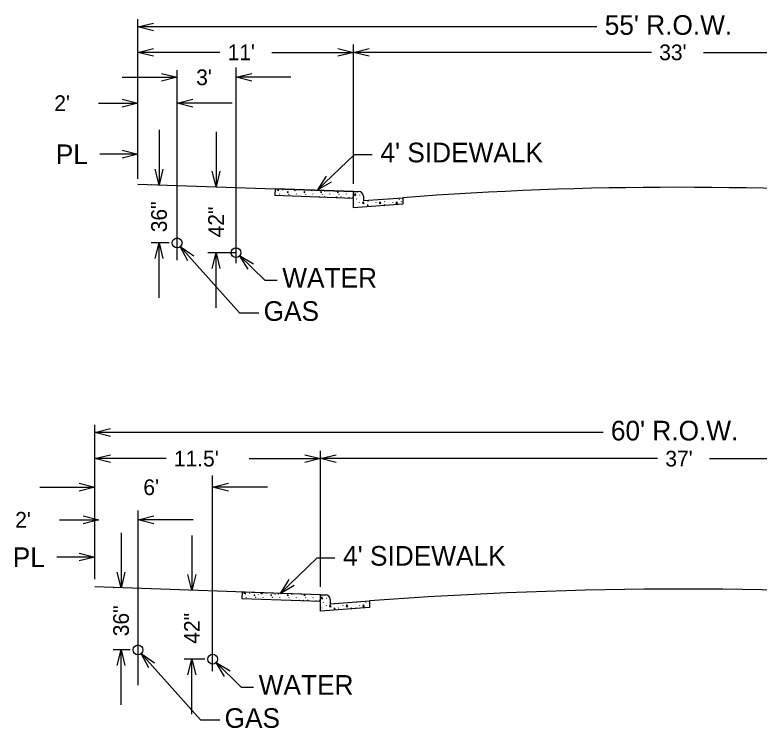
# Model space of a CAD drawing. Extents: x 524397 to 525117, y 3701341 to 3701821.
# Drawn here: x 524722.9 to 524798.7, y 3701506.1 to 3701578.8 of the extents above; entities that cross this region are included whole.
import ezdxf

# ---------------------------------------------------------------- set-up
doc = ezdxf.new("R2010")
doc.units = 0
doc.layers.add('Level 11', color=7, linetype='Continuous')

msp = doc.modelspace()

# ---------------------------------------------------------------- linework, layer by layer
at = {"layer": 'Level 11'}
for p, q in [((524735.411, 3701562.373), (524735.411, 3701578.385)), ((524735.411, 3701577.585), (524737.012, 3701577.985)), ((524782.191, 3701577.585), (524735.411, 3701577.585)), ((524737.012, 3701577.185), (524735.411, 3701577.585)), ((524735.411, 3701562.373), (524735.411, 3701575.796)), ((524757.398, 3701561.605), (524757.398, 3701575.796)), ((524735.411, 3701574.995), (524737.012, 3701575.396)), ((524743.751, 3701574.995), (524735.411, 3701574.995)), ((524737.012, 3701574.595), (524735.411, 3701574.995)), ((524749.058, 3701574.995), (524757.398, 3701574.995)), ((524755.797, 3701575.396), (524757.398, 3701574.995)), ((524757.398, 3701574.995), (524755.797, 3701574.595)), ((524757.398, 3701574.995), (524758.999, 3701575.396)), ((524787.744, 3701574.995), (524757.398, 3701574.995)), ((524758.999, 3701574.595), (524757.398, 3701574.995)), ((524793.051, 3701574.995), (524823.398, 3701574.995)), ((524745.411, 3701553.501), (524745.411, 3701573.437)), ((524737.81, 3701572.854), (524739.411, 3701572.454)), ((524739.411, 3701553.8), (524739.411, 3701573.178)), ((524745.411, 3701572.454), (524747.012, 3701572.854)), ((524733.808, 3701572.454), (524739.411, 3701572.454)), ((524739.411, 3701572.454), (524737.81, 3701572.053)), ((524751.015, 3701572.454), (524745.411, 3701572.454)), ((524747.012, 3701572.053), (524745.411, 3701572.454)), ((524731.409, 3701569.815), (524735.411, 3701569.815)), ((524733.81, 3701570.215), (524735.411, 3701569.815)), ((524735.411, 3701569.815), (524733.81, 3701569.415)), ((524739.411, 3701569.815), (524741.012, 3701570.215)), ((524745.015, 3701569.815), (524739.411, 3701569.815)), ((524741.012, 3701569.415), (524739.411, 3701569.815)), ((524735.411, 3701562.088), (524735.411, 3701569.337)), ((524739.411, 3701556.088), (524739.411, 3701569.337)), ((524737.565, 3701567.099), (524737.565, 3701561.496)), ((524743.375, 3701566.897), (524743.375, 3701561.294)), ((524733.81, 3701565.02), (524735.411, 3701564.62)), ((524735.411, 3701564.62), (524731.535, 3701564.62)), ((524735.411, 3701564.62), (524733.81, 3701564.22)), ((524753.712, 3701560.967), (524757.491, 3701564.578)), ((524757.491, 3701564.578), (524759.296, 3701564.578)), ((524737.565, 3701561.496), (524737.165, 3701563.097)), ((524737.965, 3701563.097), (524737.565, 3701561.496)), ((524743.375, 3701561.294), (524742.975, 3701562.895)), ((524743.775, 3701562.895), (524743.375, 3701561.294)), ((524754.593, 3701562.362), (524753.712, 3701560.967)), ((524735.411, 3701561.572), (524757.398, 3701560.804)), ((524736.794, 3701561.496), (524736.765, 3701561.496)), ((524742.576, 3701561.294), (524742.575, 3701561.294)), ((524753.712, 3701560.967), (524755.146, 3701561.783)), ((524749.403, 3701561.084), (524749.379, 3701560.424)), ((524757.398, 3701560.804), (524749.403, 3701561.084)), ((524749.866, 3701560.538), (524749.852, 3701560.57)), ((524750.19, 3701560.95), (524750.175, 3701560.982)), ((524750.79, 3701560.53), (524750.776, 3701560.509)), ((524750.804, 3701560.538), (524750.79, 3701560.517)), ((524751.047, 3701560.861), (524751.043, 3701560.829)), ((524751.568, 3701560.538), (524751.554, 3701560.57)), ((524751.891, 3701560.95), (524751.877, 3701560.982)), ((524752.491, 3701560.53), (524752.477, 3701560.509)), ((524752.506, 3701560.538), (524752.491, 3701560.517)), ((524752.748, 3701560.861), (524752.745, 3701560.829)), ((524753.269, 3701560.538), (524753.255, 3701560.57)), ((524754.193, 3701560.53), (524754.179, 3701560.509)), ((524754.207, 3701560.538), (524754.193, 3701560.517)), ((524754.45, 3701560.861), (524754.446, 3701560.829)), ((524754.971, 3701560.538), (524754.957, 3701560.57)), ((524755.894, 3701560.53), (524755.88, 3701560.509)), ((524755.909, 3701560.538), (524755.894, 3701560.517)), ((524756.15, 3701560.848), (524756.148, 3701560.829)), ((524756.672, 3701560.538), (524756.658, 3701560.57)), ((524757.398, 3701559.143), (524757.398, 3701560.804)), ((524757.398, 3701560.804), (524757.911, 3701560.804)), ((524757.398, 3701560.144), (524757.398, 3701560.804)), ((524757.911, 3701560.804), (524757.898, 3701560.804)), ((524758.04, 3701560.445), (524758.026, 3701560.477)), ((524749.379, 3701560.424), (524757.398, 3701560.144)), ((524754.417, 3701560.275), (524754.403, 3701560.307)), ((524755.247, 3701560.219), (524755.244, 3701560.225)), ((524756.118, 3701560.275), (524756.104, 3701560.307)), ((524756.96, 3701560.193), (524756.946, 3701560.225)), ((524757.717, 3701560.033), (524757.703, 3701560.065)), ((524758.005, 3701559.688), (524757.99, 3701559.72)), ((524758.398, 3701560.342), (524758.398, 3701559.88)), ((524758.398, 3701559.88), (524762.398, 3701560.182)), ((524758.864, 3701559.77), (524758.85, 3701559.802)), ((524759.706, 3701559.688), (524759.692, 3701559.72)), ((524760.342, 3701560.025), (524760.328, 3701560.004)), ((524760.352, 3701560.027), (524760.342, 3701560.012)), ((524760.566, 3701559.77), (524760.551, 3701559.802)), ((524761.12, 3701560.033), (524761.106, 3701560.065)), ((524761.408, 3701559.688), (524761.393, 3701559.72)), ((524762.043, 3701560.025), (524762.029, 3701560.004)), ((524762.058, 3701560.033), (524762.043, 3701560.012)), ((524762.267, 3701559.77), (524762.253, 3701559.802)), ((524762.398, 3701560.182), (524762.398, 3701559.52)), ((524762.398, 3701559.52), (524757.398, 3701559.143)), ((524757.561, 3701559.461), (524757.546, 3701559.44)), ((524759.262, 3701559.461), (524759.248, 3701559.44)), ((524760.964, 3701559.461), (524760.949, 3701559.44)), ((524738.611, 3701555.572), (524736.765, 3701555.572)), ((524737.165, 3701553.971), (524737.565, 3701555.572)), ((524737.565, 3701549.968), (524737.565, 3701555.572)), ((524737.565, 3701555.572), (524737.965, 3701553.971)), ((524739.411, 3701555.464), (524739.411, 3701555.549)), ((524740.503, 3701553.731), (524739.736, 3701555.192)), ((524739.736, 3701555.192), (524741.1, 3701554.264)), ((524739.736, 3701555.192), (524745.766, 3701548.436)), ((524745.411, 3701554.568), (524742.549, 3701554.568)), ((524744.611, 3701554.572), (524742.575, 3701554.572)), ((524742.975, 3701552.971), (524743.375, 3701554.572)), ((524743.375, 3701548.968), (524743.375, 3701554.572)), ((524743.375, 3701554.572), (524743.775, 3701552.971)), ((524746.649, 3701552.879), (524745.781, 3701554.283)), ((524745.781, 3701554.283), (524747.207, 3701553.453)), ((524745.781, 3701554.283), (524748.346, 3701551.784)), ((524748.346, 3701551.784), (524749.592, 3701551.784)), ((524745.766, 3701548.436), (524747.754, 3701548.436)), ((524731.022, 3701521.302), (524731.022, 3701537.038)), ((524731.022, 3701536.238), (524732.623, 3701536.638)), ((524782.816, 3701536.238), (524731.022, 3701536.238)), ((524732.623, 3701535.838), (524731.022, 3701536.238)), ((524731.022, 3701521.302), (524731.022, 3701534.384)), ((524731.022, 3701533.584), (524732.623, 3701533.984)), ((524752.416, 3701533.984), (524754.017, 3701533.584)), ((524754.017, 3701520.499), (524754.017, 3701534.384)), ((524754.017, 3701533.584), (524755.618, 3701533.984)), ((524738.278, 3701533.584), (524731.022, 3701533.584)), ((524732.623, 3701533.183), (524731.022, 3701533.584)), ((524746.762, 3701533.584), (524754.017, 3701533.584)), ((524754.017, 3701533.584), (524752.416, 3701533.183)), ((524788.366, 3701533.584), (524754.017, 3701533.584)), ((524755.618, 3701533.183), (524754.017, 3701533.584)), ((524793.673, 3701533.584), (524828.022, 3701533.584)), ((524743.03, 3701511.919), (524743.03, 3701531.856)), ((524729.421, 3701531.071), (524731.022, 3701530.671)), ((524743.03, 3701530.671), (524744.631, 3701531.071)), ((524725.419, 3701530.671), (524731.022, 3701530.671)), ((524731.022, 3701530.671), (524729.421, 3701530.271)), ((524748.634, 3701530.671), (524743.03, 3701530.671)), ((524744.631, 3701530.271), (524743.03, 3701530.671)), ((524735.43, 3701510.504), (524735.43, 3701528.3)), ((524727.427, 3701527.352), (524731.43, 3701527.352)), ((524729.829, 3701527.752), (524731.43, 3701527.352)), ((524731.43, 3701527.352), (524729.829, 3701526.952)), ((524735.43, 3701527.352), (524737.031, 3701527.752)), ((524741.034, 3701527.352), (524735.43, 3701527.352)), ((524737.031, 3701526.952), (524735.43, 3701527.352)), ((524733.693, 3701526.012), (524733.693, 3701520.408)), ((524740.918, 3701525.759), (524740.918, 3701520.156)), ((524731.022, 3701523.55), (524727.146, 3701523.55)), ((524729.421, 3701523.95), (524731.022, 3701523.55)), ((524731.022, 3701523.55), (524729.421, 3701523.15)), ((524749.904, 3701519.853), (524753.683, 3701523.464)), ((524753.683, 3701523.464), (524755.488, 3701523.464)), ((524733.693, 3701520.408), (524733.292, 3701522.009)), ((524734.093, 3701522.009), (524733.693, 3701520.408)), ((524740.918, 3701520.156), (524740.518, 3701521.757)), ((524741.318, 3701521.757), (524740.918, 3701520.156)), ((524750.785, 3701521.248), (524749.904, 3701519.853)), ((524754.017, 3701519.699), (524731.022, 3701520.502)), ((524732.915, 3701520.408), (524732.892, 3701520.408)), ((524749.904, 3701519.853), (524751.338, 3701520.669)), ((524740.142, 3701520.156), (524740.118, 3701520.156)), ((524746.022, 3701519.978), (524745.999, 3701519.319)), ((524754.017, 3701519.699), (524746.022, 3701519.978)), ((524746.809, 3701519.845), (524746.795, 3701519.877)), ((524747.666, 3701519.756), (524747.663, 3701519.724)), ((524748.511, 3701519.845), (524748.497, 3701519.877)), ((524749.368, 3701519.756), (524749.364, 3701519.724)), ((524751.069, 3701519.756), (524751.066, 3701519.724)), ((524752.769, 3701519.742), (524752.767, 3701519.724)), ((524754.017, 3701518.037), (524754.017, 3701519.699)), ((524754.017, 3701519.699), (524754.531, 3701519.699)), ((524754.017, 3701519.039), (524754.017, 3701519.699)), ((524754.531, 3701519.699), (524754.517, 3701519.699)), ((524745.999, 3701519.319), (524754.017, 3701519.039)), ((524746.486, 3701519.433), (524746.472, 3701519.465)), ((524747.41, 3701519.425), (524747.395, 3701519.404)), ((524747.424, 3701519.433), (524747.41, 3701519.412)), ((524748.188, 3701519.433), (524748.173, 3701519.465)), ((524749.111, 3701519.425), (524749.097, 3701519.404)), ((524749.125, 3701519.433), (524749.111, 3701519.412)), ((524749.889, 3701519.433), (524749.875, 3701519.465)), ((524750.813, 3701519.425), (524750.798, 3701519.404)), ((524750.827, 3701519.433), (524750.813, 3701519.412)), ((524751.037, 3701519.17), (524751.022, 3701519.202)), ((524751.591, 3701519.433), (524751.576, 3701519.465)), ((524751.867, 3701519.114), (524751.864, 3701519.12)), ((524752.514, 3701519.425), (524752.5, 3701519.404)), ((524752.528, 3701519.433), (524752.514, 3701519.412)), ((524752.738, 3701519.17), (524752.724, 3701519.202)), ((524753.292, 3701519.433), (524753.278, 3701519.465)), ((524753.58, 3701519.088), (524753.566, 3701519.12)), ((524754.337, 3701518.928), (524754.322, 3701518.96)), ((524754.66, 3701519.34), (524754.646, 3701519.372)), ((524755.017, 3701519.237), (524755.017, 3701518.774)), ((524755.017, 3701518.774), (524759.017, 3701519.076)), ((524756.962, 3701518.92), (524756.947, 3701518.898)), ((524756.972, 3701518.922), (524756.962, 3701518.907)), ((524757.74, 3701518.928), (524757.725, 3701518.96)), ((524758.663, 3701518.92), (524758.649, 3701518.898)), ((524758.677, 3701518.928), (524758.663, 3701518.907)), ((524759.017, 3701519.076), (524759.017, 3701518.415)), ((524759.017, 3701518.415), (524754.017, 3701518.037)), ((524754.18, 3701518.356), (524754.166, 3701518.334)), ((524754.624, 3701518.583), (524754.61, 3701518.615)), ((524755.484, 3701518.665), (524755.47, 3701518.697)), ((524755.882, 3701518.356), (524755.868, 3701518.334)), ((524756.326, 3701518.583), (524756.312, 3701518.615)), ((524757.185, 3701518.665), (524757.171, 3701518.697)), ((524757.583, 3701518.356), (524757.569, 3701518.334)), ((524758.027, 3701518.583), (524758.013, 3701518.615)), ((524758.887, 3701518.665), (524758.873, 3701518.697)), ((524734.63, 3701514.087), (524732.892, 3701514.087)), ((524733.292, 3701512.486), (524733.693, 3701514.087)), ((524733.693, 3701508.484), (524733.693, 3701514.087)), ((524733.693, 3701514.087), (524734.093, 3701512.486)), ((524736.522, 3701512.246), (524735.754, 3701513.707)), ((524735.754, 3701513.707), (524737.119, 3701512.779)), ((524735.754, 3701513.707), (524741.785, 3701506.952)), ((524742.23, 3701513.144), (524740.118, 3701513.144)), ((524740.518, 3701511.543), (524740.918, 3701513.144)), ((524740.918, 3701507.54), (524740.918, 3701513.144)), ((524740.918, 3701513.144), (524741.318, 3701511.543)), ((524744.251, 3701511.386), (524743.383, 3701512.79)), ((524743.383, 3701512.79), (524744.809, 3701511.96)), ((524743.383, 3701512.79), (524745.948, 3701510.291)), ((524745.948, 3701510.291), (524747.194, 3701510.291)), ((524741.785, 3701506.952), (524743.772, 3701506.952))]:
    msp.add_line(p, q, dxfattribs=at)
for points in [[(524749.688, 3701561.074), (524749.602, 3701560.985), (524749.754, 3701560.915)], [(524749.758, 3701560.914), (524749.736, 3701561.072)], [(524750.722, 3701560.723), (524750.68, 3701560.812), (524750.609, 3701560.759), (524750.722, 3701560.723)], [(524751.333, 3701561.016), (524751.304, 3701560.985), (524751.456, 3701560.915)], [(524751.459, 3701560.914), (524751.445, 3701561.012)], [(524752.424, 3701560.723), (524752.381, 3701560.812), (524752.31, 3701560.759), (524752.424, 3701560.723)], [(524753.07, 3701560.955), (524753.157, 3701560.915)], [(524753.161, 3701560.914), (524753.155, 3701560.952)], [(524754.125, 3701560.723), (524754.083, 3701560.812), (524754.012, 3701560.759), (524754.125, 3701560.723)], [(524755.827, 3701560.723), (524755.784, 3701560.812), (524755.713, 3701560.759), (524755.827, 3701560.723)], [(524757.608, 3701560.409), (524757.58, 3701560.612), (524757.453, 3701560.48), (524757.605, 3701560.41)], [(524753.948, 3701560.265), (524753.941, 3701560.279), (524753.935, 3701560.265)], [(524755.682, 3701560.204), (524755.642, 3701560.279), (524755.61, 3701560.207)], [(524757.398, 3701560.177), (524757.344, 3701560.279), (524757.285, 3701560.148)], [(524758.484, 3701559.592), (524758.388, 3701559.773), (524758.314, 3701559.607), (524758.48, 3701559.592)], [(524760.186, 3701559.592), (524760.09, 3701559.773), (524760.015, 3701559.607), (524760.182, 3701559.592)], [(524761.887, 3701559.592), (524761.791, 3701559.773), (524761.717, 3701559.607), (524761.883, 3701559.592)], [(524758.073, 3701559.193), (524758.068, 3701559.203), (524758.052, 3701559.192)], [(524758.889, 3701559.369), (524758.846, 3701559.457), (524758.775, 3701559.404), (524758.889, 3701559.369)], [(524760.584, 3701559.383), (524760.548, 3701559.457), (524760.477, 3701559.404), (524760.552, 3701559.381)], [(524746.307, 3701519.968), (524746.222, 3701519.88), (524746.374, 3701519.81)], [(524746.377, 3701519.808), (524746.355, 3701519.966)], [(524747.342, 3701519.618), (524747.3, 3701519.707), (524747.229, 3701519.653), (524747.342, 3701519.618)], [(524747.953, 3701519.911), (524747.923, 3701519.88), (524748.075, 3701519.81)], [(524748.079, 3701519.808), (524748.065, 3701519.907)], [(524749.044, 3701519.618), (524749.001, 3701519.707), (524748.93, 3701519.653), (524749.044, 3701519.618)], [(524749.689, 3701519.85), (524749.777, 3701519.81)], [(524749.78, 3701519.808), (524749.775, 3701519.847)], [(524750.745, 3701519.618), (524750.703, 3701519.707), (524750.632, 3701519.653), (524750.745, 3701519.618)], [(524752.447, 3701519.618), (524752.404, 3701519.707), (524752.333, 3701519.653), (524752.447, 3701519.618)], [(524754.228, 3701519.303), (524754.199, 3701519.506), (524754.072, 3701519.375), (524754.224, 3701519.304)], [(524750.568, 3701519.159), (524750.56, 3701519.173), (524750.554, 3701519.16)], [(524752.301, 3701519.099), (524752.262, 3701519.173), (524752.23, 3701519.101)], [(524754.017, 3701519.071), (524753.963, 3701519.173), (524753.905, 3701519.043)], [(524754.692, 3701518.088), (524754.687, 3701518.098), (524754.672, 3701518.087)], [(524755.104, 3701518.487), (524755.008, 3701518.668), (524754.933, 3701518.501), (524755.1, 3701518.487)], [(524755.509, 3701518.263), (524755.466, 3701518.352), (524755.395, 3701518.299), (524755.509, 3701518.263)], [(524756.805, 3701518.487), (524756.709, 3701518.668), (524756.635, 3701518.501), (524756.802, 3701518.487)], [(524757.203, 3701518.278), (524757.168, 3701518.352), (524757.097, 3701518.299), (524757.172, 3701518.275)], [(524758.507, 3701518.487), (524758.411, 3701518.668), (524758.336, 3701518.501), (524758.503, 3701518.487)]]:
    msp.add_lwpolyline(points, dxfattribs=at)
for centre in [(524739.411, 3701555.572), (524745.411, 3701554.572), (524735.43, 3701514.087), (524743.03, 3701513.144)]:
    msp.add_circle(centre, 0.5, dxfattribs=at)
for centre, radius, start, end in [((524790.397, 3701189.335), 371.902, 85.68204, 94.31764), ((524757.904, 3701560.31), 0.494, 3.70795, 90.76675), ((524791.02, 3701095.204), 425.079, 85.68236, 94.31764), ((524754.524, 3701519.205), 0.494, 3.70795, 90.76675)]:
    msp.add_arc(centre, radius, start, end, dxfattribs=at)

# ---------------------------------------------------------------- texts
for s, height, p in [("55' R.O.W.", 2, (524782.992, 3701576.783)), ("11'", 1.601, (524744.551, 3701574.194)), ("33'", 1.601, (524788.545, 3701574.194)), ("3'", 1.601, (524741.353, 3701571.652)), ("2'", 1.601, (524726.89, 3701569.013)), ("4' SIDEWALK", 2, (524760.133, 3701563.787)), ('PL', 2, (524727.044, 3701563.602)), ('WATER', 2, (524750.126, 3701551.011)), ('GAS', 2, (524748.228, 3701547.628)), ("60' R.O.W.", 2, (524783.616, 3701535.437)), ("11.5'", 1.601, (524739.078, 3701532.783)), ("37'", 1.601, (524789.167, 3701532.783)), ("6'", 1.601, (524735.967, 3701529.869)), ("2'", 1.601, (524722.908, 3701526.551)), ('PL', 2, (524722.655, 3701522.532)), ("4' SIDEWALK", 2, (524756.325, 3701522.673)), ('WATER', 2, (524747.727, 3701509.518)), ('GAS', 2, (524744.246, 3701506.143))]:
    msp.add_text(s, height=height, dxfattribs=at).set_placement(p)
for s, p in [('36"', (524738.365, 3701556.655)), ('42"', (524744.176, 3701556.136)), ('36"', (524734.493, 3701515.478)), ('42"', (524741.718, 3701514.717))]:
    msp.add_text(s, height=1.601, rotation=90, dxfattribs=at).set_placement(p)

doc.saveas('drawing.dxf')
